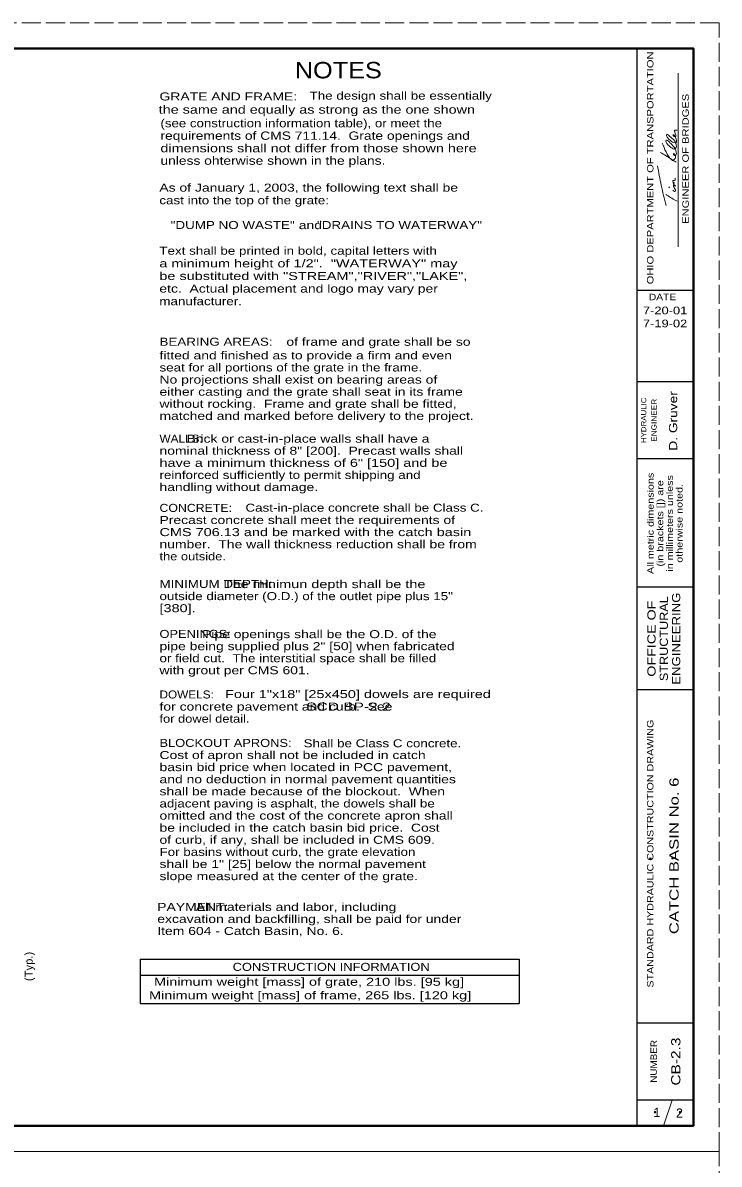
# Model space of a CAD drawing. Extents: x 1083.1 to 1117.1, y 719.4 to 763.4.
# Drawn here: x 1103.56 to 1117.13, y 741.1 to 763.35 of the extents above; entities that cross this region are included whole.
import ezdxf
from ezdxf.enums import TextEntityAlignment as Align

# ---------------------------------------------------------------- set-up
doc = ezdxf.new("R2010")
doc.units = 0
doc.header["$LTSCALE"] = 0.062
doc.header["$PDMODE"] = 32
doc.header["$PDSIZE"] = 0.031
doc.linetypes.add('LONG_DASHED', pattern=[7.5, 6, -1.5])
doc.layers.add('1', color=7, linetype='Continuous', lineweight=13)

msp = doc.modelspace()

# ---------------------------------------------------------------- linework, layer by layer
at = {"layer": '1', "lineweight": 25}
for p, q in [((1085.12642, 762.85408), (1116.62642, 762.85408)), ((1115.52642, 741.85408), (1115.52642, 762.85408)), ((1116.62642, 762.85408), (1116.62642, 741.85408)), ((1116.62642, 758.13825), (1115.52642, 758.13825)), ((1116.62642, 756.35408), (1115.52642, 756.35408)), ((1116.62642, 754.85408), (1115.52642, 754.85408)), ((1116.62642, 752.35408), (1115.52642, 752.35408)), ((1116.62642, 750.35408), (1115.52642, 750.35408)), ((1105.84925, 745.10342), (1113.22992, 745.10342)), ((1105.84925, 745.10342), (1105.84925, 744.23767)), ((1113.22992, 745.10342), (1113.22992, 744.23767)), ((1105.84925, 744.78858), (1113.22992, 744.78858)), ((1105.84925, 744.23767), (1113.22992, 744.23767)), ((1116.62642, 743.85408), (1115.52642, 743.85408)), ((1116.62642, 742.35408), (1115.52642, 742.35408))]:
    msp.add_line(p, q, dxfattribs=at)
at = {"layer": '1'}
for p, q in [((1116.32517, 758.98508), (1116.32517, 762.37517)), ((1116.15767, 760.136), (1116.1475, 760.15525)), ((1116.04308, 741.85408), (1116.20975, 742.35408))]:
    msp.add_line(p, q, dxfattribs=at)
at = {"layer": '1', "linetype": 'LONG_DASHED'}
for points in [[(1083.12642, 741.35408), (1117.12642, 741.35408), (1117.12642, 763.35408), (1083.12642, 763.35408)], [(1083.12642, 719.35408), (1117.12642, 719.35408), (1117.12642, 741.35408), (1083.12642, 741.35408)]]:
    msp.add_lwpolyline(points, close=True, dxfattribs=at)
at = {"layer": '1', "lineweight": 25}
msp.add_lwpolyline([(1116.62642, 741.85408), (1085.12642, 741.85408), (1085.12642, 762.85408)], dxfattribs=at)
at = {"layer": '1', "lineweight": 40}
msp.add_lwpolyline([(1085.12642, 762.85408), (1116.62642, 762.85408), (1116.62642, 741.85408), (1085.12642, 741.85408)], close=True, dxfattribs=at)
msp.add_lwpolyline([(1085.12642, 762.85408), (1116.62642, 762.85408), (1116.62642, 741.85408), (1085.12642, 741.85408)], close=True, dxfattribs=at)
at = {"layer": '1'}
for points in [[(1116.01825, 761.01108), (1116.20142, 760.68275), (1116.21658, 760.67217), (1116.22675, 760.67217), (1116.25867, 760.69583), (1116.27375, 760.73), (1116.26875, 760.78125), (1116.25183, 760.80308), (1116.23833, 760.80308), (1116.23658, 760.79008), (1116.24675, 760.77492), (1116.26025, 760.7665), (1116.27533, 760.7665), (1116.2905, 760.78808), (1116.29392, 760.80742), (1116.28367, 760.86275), (1116.20142, 760.98317), (1116.15592, 761.02783), (1116.119, 761.06242), (1116.09383, 761.06458), (1116.09558, 761.026), (1116.12075, 760.98725), (1116.188, 760.92492), (1116.23008, 760.8995), (1116.26375, 760.895), (1116.28708, 760.921), (1116.29392, 760.95517), (1116.28883, 760.98092), (1116.25867, 761.05408), (1116.22842, 761.08608), (1116.16783, 761.1395), (1116.13917, 761.16533), (1116.10567, 761.18058), (1116.10225, 761.15258), (1116.11233, 761.12675), (1116.1695, 761.06683), (1116.24017, 761.01958), (1116.29217, 761.02192), (1116.2905, 761.07958), (1116.27867, 761.1225), (1116.26533, 761.14825), (1116.25517, 761.159), (1116.23175, 761.174), (1116.2335, 761.15692), (1116.26875, 761.13542), (1116.28367, 761.14617), (1116.27058, 761.19983), (1116.262, 761.22775), (1116.25867, 761.24042), (1116.25867, 761.25325), (1116.25867, 761.26192), (1116.28367, 761.25975), (1116.30908, 761.25975)], [(1115.97942, 760.82883), (1116.20317, 760.69133), (1116.28883, 760.63567)], [(1116.09567, 759.79183), (1115.997, 760.18708), (1115.92575, 760.56942)], [(1116.22675, 760.09075), (1116.235, 760.08008), (1116.27217, 760.06717), (1116.27692, 760.09958), (1116.25183, 760.136), (1116.23658, 760.17225), (1116.23658, 760.1915), (1116.25183, 760.18525), (1116.262, 760.17442), (1116.27217, 760.17008), (1116.2485, 760.20225), (1116.23658, 760.21725), (1116.2335, 760.23458), (1116.25692, 760.228), (1116.2485, 760.23667), (1116.22333, 760.2645), (1116.2335, 760.27967), (1116.25025, 760.28167), (1116.25867, 760.27967), (1116.26875, 760.301), (1116.262, 760.32892)], [(1116.31083, 759.87625), (1116.10567, 759.99625), (1116.09008, 760.00667)]]:
    msp.add_spline(points, degree=3, dxfattribs=at)
for p in [(1115.78383, 747.06008), (1116.21667, 747.06742), (1115.8745, 742.11783), (1116.36292, 742.11683)]:
    msp.add_point(p, dxfattribs=at)

# ---------------------------------------------------------------- texts
for s, height, width, p in [('OHIO DEPARTMENT OF TRANSPORTATION', 0.125, 1.3, (1115.84633, 760.52633)), ('ENGINEER OF BRIDGES', 0.125, 1.3, (1116.53467, 760.70312)), ('D. Gruver', 0.16, 1.25, (1116.30875, 755.59333)), ('HYDRAULIC', 0.1, 1.15, (1115.7055, 755.60517)), ('ENGINEER', 0.1, 1.2, (1115.90642, 755.60521)), ('All metric dimensions', 0.125, 1.25, (1115.85025, 753.59617)), ('in millimeters unless', 0.125, 1.25, (1116.22525, 753.59621)), ('(in brackets []) are', 0.125, 1.25, (1116.03775, 753.59617)), ('otherwise noted.', 0.125, 1.25, (1116.41275, 753.59617)), ('OFFICE OF', 0.16, 1.3, (1115.88817, 751.34854)), ('STRUCTURAL', 0.16, 1.15, (1116.12817, 751.34854)), ('ENGINEERING', 0.16, 1.2, (1116.36817, 751.34862)), ('STANDARD HYDRAULIC CONSTRUCTION DRAWING', 0.125, 1.25, (1115.84633, 747.15812)), ('CATCH BASIN No. 6', 0.18, 1.35, (1116.337, 747.11425)), ('(Typ.)', 0.156, 1.05, (1103.75167, 744.95896)), ('NUMBER', 0.125, 1.15, (1115.91342, 743.10817)), ('CB-2.3', 0.18, 1.25, (1116.37158, 743.10438))]:
    msp.add_text(s, height=height, rotation=90, dxfattribs=dict(at, width=width)).set_placement(p, align=Align.CENTER)
for s, height, width, p in [('NOTES', 0.32, 1.15, (1108.85867, 762.27175)), ('GRATE AND FRAME:', 0.156, 1.3, (1106.22267, 761.84075)), ('The design shall be essentially', 0.156, 1.25, (1109.14658, 761.85642)), ('the same and equally as strong as the one shown', 0.161, 1.3, (1106.20792, 761.58275)), ('(see construction information table), or meet the', 0.161, 1.2, (1106.24117, 761.31758)), ('requirements of CMS 711.14.  Grate openings and ', 0.161, 1.25, (1106.24117, 761.07392)), ('dimensions shall not differ from those shown here ', 0.161, 1.3, (1106.24117, 760.83042)), ('unless ohterwise shown in the plans.', 0.161, 1.25, (1106.24117, 760.58675)), ('As of January 1, 2003, the following text shall be ', 0.156, 1.3, (1106.22025, 760.06308)), ('cast into the top of the grate: ', 0.156, 1.25, (1106.22025, 759.81708)), ('   "DUMP NO WASTE"      "DRAINS TO WATERWAY"', 0.156, 1.25, (1106.22408, 759.33458)), (' and', 0.156, 1.3, (1108.86092, 759.332)), ('Text shall be printed in bold, capital letters with ', 0.156, 1.25, (1106.22025, 758.83308)), ('a minimum height of 1/2".  "WATERWAY" may ', 0.156, 1.35, (1106.22025, 758.58708)), ('be substituted with "STREAM","RIVER","LAKE", ', 0.156, 1.35, (1106.22025, 758.34108)), ('etc.  Actual placement and logo may vary per ', 0.156, 1.3, (1106.22025, 758.09508)), ('manufacturer.', 0.156, 1.25, (1106.22025, 757.84908)), ('BEARING AREAS:', 0.156, 1.25, (1106.22275, 757.05925)), ('of frame and grate shall be so', 0.156, 1.3, (1108.69492, 757.05825)), ('fitted and finished as to provide a firm and even', 0.156, 1.3, (1106.22275, 756.79333)), ('seat for all portions of the grate in the frame.', 0.156, 1.25, (1106.22275, 756.55725)), ('No projections shall exist on bearing areas of', 0.156, 1.3, (1106.22275, 756.32117)), ('either casting and the grate shall seat in its frame', 0.156, 1.3, (1106.22275, 756.085)), ('without rocking.  Frame and grate shall be fitted,', 0.156, 1.3, (1106.22275, 755.84892)), ('matched and marked before delivery to the project.', 0.156, 1.3, (1106.22275, 755.61283)), ('WALLS:', 0.156, 1.1, (1106.22275, 755.17042)), ('       Brick or cast-in-place walls shall have a ', 0.156, 1.3, (1106.22275, 755.169)), ('nominal thickness of 8" [200].  Precast walls shall', 0.156, 1.3, (1106.22275, 754.93433)), ('have a minimum thickness of 6" [150] and be', 0.156, 1.35, (1106.22275, 754.69825)), ('reinforced sufficiently to permit shipping and', 0.156, 1.25, (1106.22275, 754.46208)), ('handling without damage.  ', 0.156, 1.3, (1106.22275, 754.226)), ('CONCRETE:', 0.156, 1.15, (1106.22275, 753.81992)), ('Cast-in-place concrete shall be Class C.', 0.156, 1.25, (1107.8975, 753.82383)), ('Precast concrete shall meet the requirements of', 0.156, 1.3, (1106.22275, 753.58383)), ('CMS 706.13 and be marked with the catch basin', 0.156, 1.35, (1106.22275, 753.34767)), ('number.  The wall thickness reduction shall be from', 0.156, 1.3, (1106.22275, 753.11158)), ('the outside.', 0.156, 1.2, (1106.22275, 752.8755)), ('                The minimun depth shall be the', 0.156, 1.35, (1106.22275, 752.33433)), ('MINIMUM DEPTH:', 0.156, 1.25, (1106.22275, 752.33725)), ('outside diameter (O.D.) of the outlet pipe plus 15"', 0.156, 1.25, (1106.22275, 752.09967)), ('[380]. ', 0.156, 1.35, (1106.22275, 751.865)), ('OPENINGS:', 0.156, 1.2, (1106.22275, 751.363)), ('           Pipe openings shall be the O.D. of the', 0.156, 1.3, (1106.22275, 751.35875)), ('pipe being supplied plus 2" [50] when fabricated', 0.156, 1.3, (1106.22275, 751.12408)), ('or field cut.  The interstitial space shall be filled', 0.156, 1.25, (1106.22275, 750.88942)), ('with grout per CMS 601.', 0.156, 1.3, (1106.22275, 750.65475)), ('DOWELS:', 0.156, 1.1, (1106.22275, 750.1825)), ('Four 1"x18" [25x450] dowels are required', 0.156, 1.35, (1107.49992, 750.19008)), ('for concrete pavement and curb.  See', 0.156, 1.3, (1106.22275, 749.94642)), ('                                  SCD BP-2.2', 0.156, 1.45, (1106.22275, 749.94642)), ('for dowel detail.', 0.156, 1.2, (1106.22275, 749.71033)), ('BLOCKOUT APRONS:', 0.156, 1.2, (1106.22275, 749.23817)), ('Shall be Class C concrete.', 0.156, 1.25, (1109.03008, 749.23125)), ('Cost of apron shall not be included in catch', 0.156, 1.3, (1106.22275, 749.002)), ('basin bid price when located in PCC pavement,', 0.156, 1.3, (1106.22275, 748.76592)), ('and no deduction in normal pavement quantities', 0.156, 1.3, (1106.22275, 748.52983)), ('shall be made because of the blockout.  When', 0.156, 1.3, (1106.22275, 748.29375)), ('adjacent paving is asphalt, the dowels shall be', 0.156, 1.25, (1106.22275, 748.05767)), ('omitted and the cost of the concrete apron shall', 0.156, 1.3, (1106.22275, 747.8215)), ('be included in the catch basin bid price.  Cost', 0.156, 1.3, (1106.22275, 747.58542)), ('of curb, if any, shall be included in CMS 609.', 0.156, 1.3, (1106.22275, 747.34933)), ('For basins without curb, the grate elevation', 0.156, 1.25, (1106.22275, 747.11325)), ('shall be 1" [25] below the normal pavement', 0.156, 1.3, (1106.22275, 746.87717)), ('slope measured at the center of the grate.', 0.156, 1.3, (1106.22275, 746.641)), ('PAYMENT: ', 0.156, 1.3, (1106.17917, 746.04058)), ('          All materials and labor, including', 0.156, 1.3, (1106.17917, 746.04058)), ('excavation and backfilling, shall be paid for under ', 0.156, 1.3, (1106.17917, 745.80658)), ('Item 604 - Catch Basin, No. 6.', 0.156, 1.3, (1106.17917, 745.57258)), ('Minimum weight [mass] of grate, 210 lbs. [95 kg]', 0.156, 1.35, (1106.1155, 744.58183)), ('Minimum weight [mass] of frame, 265 lbs. [120 kg]', 0.156, 1.35, (1106.01925, 744.31883))]:
    msp.add_text(s, height=height, dxfattribs=dict(at, width=width)).set_placement(p)
for s, height, width, p in [('DATE', 0.125, 1.2, (1116.02312, 757.94683)), ('7-20-01', 0.15, 1.25, (1116.07346, 757.67133)), ('7-19-02', 0.15, 1.25, (1116.07346, 757.41825)), ('CONSTRUCTION INFORMATION', 0.156, 1.2, (1109.56754, 744.87267))]:
    msp.add_text(s, height=height, dxfattribs=dict(at, width=width)).set_placement(p, align=Align.CENTER)
for s, p in [('1', (1115.91427, 742.02417)), ('2', (1116.35371, 742.01158))]:
    msp.add_text(s, height=0.18, dxfattribs=at).set_placement(p, align=Align.CENTER)

doc.saveas('drawing.dxf')
